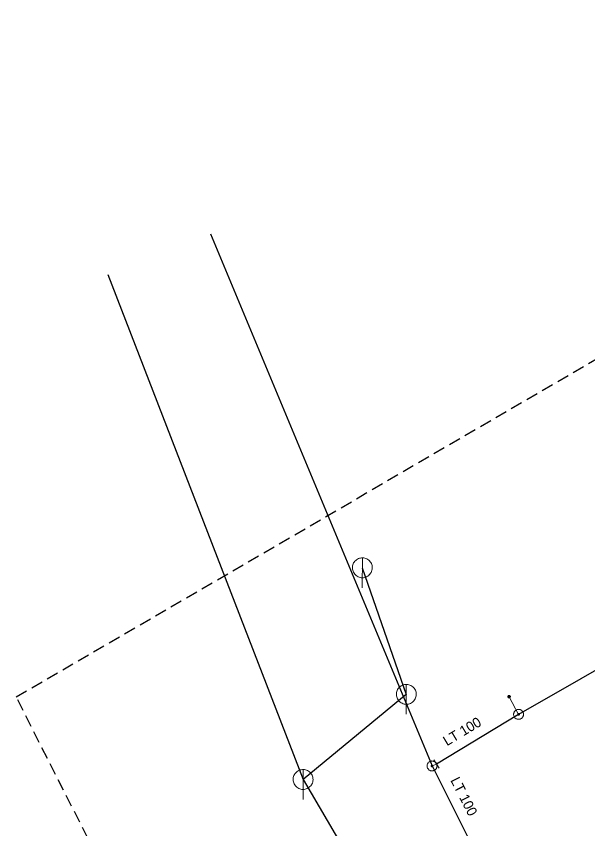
# Model space of a CAD drawing. Extents: x -689189 to -688666, y -973229 to -972850.
# Drawn here: x -689187.5 to -689130.1, y -973144.4 to -973062.7 of the extents above; entities that cross this region are included whole.
import ezdxf

# ---------------------------------------------------------------- set-up
doc = ezdxf.new("R2010")
doc.units = 0
doc.header["$LTSCALE"] = 0.4
doc.linetypes.add('MEDIUM_DASHED', pattern=[4.5, 3, -1.5])
doc.layers.add('1', color=7, linetype='Continuous')
for name, color, linetype, lineweight in [('14', 7, 'Continuous', 13), ('17', 7, 'Continuous', 25), ('22', 7, 'Continuous', 13), ('34', 7, 'Continuous', 13), ('47', 7, 'Continuous', 13), ('63', 7, 'MEDIUM_DASHED', 25), ('9', 7, 'Continuous', 13)]:
    doc.layers.add(name, color=color, linetype=linetype, lineweight=lineweight)

msp = doc.modelspace()

# ---------------------------------------------------------------- linework, layer by layer
at = {"layer": '14', "lineweight": 25}
for p, q in [((-689178.322, -973088.675), (-689158.682, -973139.478)), ((-689152.725, -973118.185), (-689148.304, -973130.915)), ((-689148.304, -973130.915), (-689158.682, -973139.478)), ((-689158.682, -973139.478), (-689148.953, -973156.032))]:
    msp.add_line(p, q, dxfattribs=at)
at = {"layer": '14'}
for p, q in [((-689137.019, -973132.93), (-689137.97, -973131.15)), ((-689145.719, -973138.12), (-689145.277, -973137.93))]:
    msp.add_line(p, q, dxfattribs=at)
at = {"layer": '17'}
for p, q in [((-689167.984, -973084.593), (-689145.719, -973138.12)), ((-689137.019, -973132.93), (-689145.277, -973137.93)), ((-689145.719, -973138.12), (-689141.14, -973147.239))]:
    msp.add_line(p, q, dxfattribs=at)
msp.add_lwpolyline([(-688981.288, -973042.24), (-688991.359, -973047.32), (-689025.954, -973066.95), (-689093.62, -973108.102), (-689137.019, -973132.93)], dxfattribs=at)
at = {"layer": '22'}
for p, q in [((-689152.725, -973120.185), (-689152.724, -973117.185)), ((-689148.304, -973132.915), (-689148.303, -973129.915)), ((-689158.682, -973141.478), (-689158.681, -973138.478))]:
    msp.add_line(p, q, dxfattribs=at)
for points in [[(-689151.725, -973118.185), (-689151.73, -973118.076), (-689151.748, -973117.968), (-689151.778, -973117.862), (-689151.818, -973117.761), (-689151.87, -973117.664), (-689151.932, -973117.574), (-689152.004, -973117.491), (-689152.084, -973117.417), (-689152.172, -973117.351), (-689152.266, -973117.296), (-689152.366, -973117.251), (-689152.471, -973117.218), (-689152.578, -973117.196), (-689152.687, -973117.186), (-689152.797, -973117.188), (-689152.905, -973117.202), (-689153.012, -973117.227), (-689153.115, -973117.264), (-689153.213, -973117.313), (-689153.305, -973117.371), (-689153.391, -973117.44), (-689153.468, -973117.517), (-689153.537, -973117.603), (-689153.596, -973117.695), (-689153.644, -973117.793), (-689153.681, -973117.896), (-689153.707, -973118.003), (-689153.721, -973118.111), (-689153.724, -973118.221), (-689153.714, -973118.33), (-689153.693, -973118.437), (-689153.659, -973118.541), (-689153.615, -973118.641), (-689153.56, -973118.736), (-689153.494, -973118.824), (-689153.42, -973118.904), (-689153.337, -973118.976), (-689153.247, -973119.038), (-689153.151, -973119.09), (-689153.049, -973119.131), (-689152.944, -973119.161), (-689152.836, -973119.179), (-689152.726, -973119.185), (-689152.617, -973119.179), (-689152.509, -973119.161), (-689152.404, -973119.132), (-689152.302, -973119.091), (-689152.205, -973119.039), (-689152.115, -973118.977), (-689152.032, -973118.906), (-689151.957, -973118.826), (-689151.892, -973118.738), (-689151.836, -973118.644), (-689151.792, -973118.544), (-689151.758, -973118.44), (-689151.736, -973118.332), (-689151.726, -973118.223)], [(-689147.304, -973130.915), (-689147.309, -973130.806), (-689147.327, -973130.698), (-689147.357, -973130.592), (-689147.397, -973130.491), (-689147.449, -973130.394), (-689147.511, -973130.304), (-689147.583, -973130.221), (-689147.663, -973130.147), (-689147.751, -973130.081), (-689147.845, -973130.026), (-689147.945, -973129.981), (-689148.05, -973129.948), (-689148.157, -973129.926), (-689148.266, -973129.916), (-689148.376, -973129.918), (-689148.484, -973129.932), (-689148.591, -973129.957), (-689148.694, -973129.994), (-689148.792, -973130.043), (-689148.884, -973130.101), (-689148.97, -973130.17), (-689149.047, -973130.247), (-689149.116, -973130.333), (-689149.175, -973130.425), (-689149.223, -973130.523), (-689149.26, -973130.626), (-689149.286, -973130.733), (-689149.3, -973130.841), (-689149.303, -973130.951), (-689149.293, -973131.06), (-689149.272, -973131.167), (-689149.238, -973131.271), (-689149.194, -973131.371), (-689149.139, -973131.466), (-689149.073, -973131.554), (-689148.999, -973131.634), (-689148.916, -973131.706), (-689148.826, -973131.768), (-689148.73, -973131.82), (-689148.628, -973131.861), (-689148.523, -973131.891), (-689148.415, -973131.909), (-689148.305, -973131.915), (-689148.196, -973131.909), (-689148.088, -973131.891), (-689147.983, -973131.862), (-689147.881, -973131.821), (-689147.784, -973131.769), (-689147.694, -973131.707), (-689147.611, -973131.636), (-689147.536, -973131.556), (-689147.471, -973131.468), (-689147.415, -973131.374), (-689147.371, -973131.274), (-689147.337, -973131.17), (-689147.315, -973131.062), (-689147.305, -973130.953)], [(-689157.682, -973139.478), (-689157.687, -973139.369), (-689157.705, -973139.261), (-689157.735, -973139.155), (-689157.775, -973139.054), (-689157.827, -973138.957), (-689157.889, -973138.867), (-689157.961, -973138.784), (-689158.041, -973138.71), (-689158.129, -973138.644), (-689158.223, -973138.589), (-689158.323, -973138.544), (-689158.428, -973138.511), (-689158.535, -973138.489), (-689158.644, -973138.479), (-689158.754, -973138.481), (-689158.862, -973138.495), (-689158.969, -973138.52), (-689159.072, -973138.557), (-689159.17, -973138.606), (-689159.262, -973138.664), (-689159.348, -973138.733), (-689159.425, -973138.81), (-689159.494, -973138.896), (-689159.553, -973138.988), (-689159.601, -973139.086), (-689159.638, -973139.189), (-689159.664, -973139.296), (-689159.678, -973139.404), (-689159.681, -973139.514), (-689159.671, -973139.623), (-689159.65, -973139.73), (-689159.616, -973139.834), (-689159.572, -973139.934), (-689159.517, -973140.029), (-689159.451, -973140.117), (-689159.377, -973140.197), (-689159.294, -973140.269), (-689159.204, -973140.331), (-689159.108, -973140.383), (-689159.006, -973140.424), (-689158.901, -973140.454), (-689158.793, -973140.472), (-689158.683, -973140.478), (-689158.574, -973140.472), (-689158.466, -973140.454), (-689158.361, -973140.425), (-689158.259, -973140.384), (-689158.162, -973140.332), (-689158.072, -973140.27), (-689157.989, -973140.199), (-689157.914, -973140.119), (-689157.849, -973140.031), (-689157.793, -973139.937), (-689157.749, -973139.837), (-689157.715, -973139.733), (-689157.693, -973139.625), (-689157.683, -973139.516)]]:
    msp.add_lwpolyline(points, close=True, dxfattribs=at)
at = {"layer": '34'}
msp.add_line((-689145.536, -973137.502), (-689145.018, -973138.357), dxfattribs=at)
at = {"layer": '47'}
for points in [[(-689136.587, -973132.676), (-689136.616, -973132.633), (-689136.65, -973132.592), (-689136.687, -973132.556), (-689136.727, -973132.523), (-689136.772, -973132.495), (-689136.819, -973132.471), (-689136.868, -973132.454), (-689136.918, -973132.44), (-689136.97, -973132.432), (-689137.022, -973132.43), (-689137.075, -973132.433), (-689137.126, -973132.442), (-689137.176, -973132.455), (-689137.225, -973132.475), (-689137.272, -973132.498), (-689137.315, -973132.527), (-689137.356, -973132.561), (-689137.393, -973132.598), (-689137.425, -973132.638), (-689137.453, -973132.683), (-689137.477, -973132.73), (-689137.495, -973132.779), (-689137.508, -973132.83), (-689137.517, -973132.881), (-689137.518, -973132.933), (-689137.515, -973132.986), (-689137.507, -973133.038), (-689137.493, -973133.087), (-689137.473, -973133.136), (-689137.45, -973133.183), (-689137.421, -973133.226), (-689137.387, -973133.267), (-689137.35, -973133.304), (-689137.31, -973133.336), (-689137.265, -973133.364), (-689137.219, -973133.388), (-689137.17, -973133.407), (-689137.119, -973133.42), (-689137.067, -973133.428), (-689137.015, -973133.429), (-689136.962, -973133.426), (-689136.911, -973133.418), (-689136.861, -973133.404), (-689136.812, -973133.384), (-689136.765, -973133.361), (-689136.722, -973133.332), (-689136.681, -973133.298), (-689136.645, -973133.262), (-689136.612, -973133.221), (-689136.584, -973133.176), (-689136.56, -973133.13), (-689136.542, -973133.081), (-689136.529, -973133.03), (-689136.521, -973132.978), (-689136.519, -973132.926), (-689136.522, -973132.873), (-689136.53, -973132.823), (-689136.544, -973132.772), (-689136.564, -973132.723)], [(-689136.948, -973132.888), (-689136.952, -973132.88), (-689136.958, -973132.874), (-689136.964, -973132.868), (-689136.971, -973132.863), (-689136.978, -973132.858), (-689136.986, -973132.855), (-689136.994, -973132.851), (-689137.002, -973132.849), (-689137.011, -973132.848), (-689137.019, -973132.848), (-689137.028, -973132.848), (-689137.036, -973132.85), (-689137.044, -973132.852), (-689137.052, -973132.854), (-689137.06, -973132.859), (-689137.068, -973132.863), (-689137.074, -973132.869), (-689137.08, -973132.875), (-689137.085, -973132.882), (-689137.09, -973132.889), (-689137.093, -973132.897), (-689137.097, -973132.905), (-689137.099, -973132.913), (-689137.101, -973132.922), (-689137.1, -973132.93), (-689137.1, -973132.939), (-689137.098, -973132.947), (-689137.096, -973132.955), (-689137.094, -973132.963), (-689137.089, -973132.971), (-689137.085, -973132.979), (-689137.079, -973132.985), (-689137.073, -973132.991), (-689137.066, -973132.996), (-689137.059, -973133.001), (-689137.052, -973133.005), (-689137.043, -973133.008), (-689137.035, -973133.01), (-689137.026, -973133.012), (-689137.018, -973133.011), (-689137.009, -973133.011), (-689137.001, -973133.009), (-689136.993, -973133.007), (-689136.985, -973133.005), (-689136.977, -973133), (-689136.969, -973132.996), (-689136.963, -973132.99), (-689136.957, -973132.984), (-689136.952, -973132.977), (-689136.947, -973132.97), (-689136.943, -973132.963), (-689136.94, -973132.954), (-689136.938, -973132.946), (-689136.937, -973132.937), (-689136.937, -973132.929), (-689136.937, -973132.92), (-689136.939, -973132.912), (-689136.941, -973132.904), (-689136.943, -973132.896)], [(-689145.51, -973138.574), (-689145.464, -973138.549), (-689145.42, -973138.521), (-689145.38, -973138.487), (-689145.343, -973138.45), (-689145.311, -973138.409), (-689145.283, -973138.364), (-689145.26, -973138.317), (-689145.242, -973138.268), (-689145.229, -973138.218), (-689145.221, -973138.166), (-689145.218, -973138.113), (-689145.223, -973138.061), (-689145.231, -973138.01), (-689145.245, -973137.959), (-689145.264, -973137.911), (-689145.289, -973137.865), (-689145.317, -973137.821), (-689145.351, -973137.78), (-689145.388, -973137.744), (-689145.429, -973137.712), (-689145.474, -973137.684), (-689145.521, -973137.66), (-689145.57, -973137.642), (-689145.62, -973137.629), (-689145.672, -973137.622), (-689145.725, -973137.619), (-689145.777, -973137.623), (-689145.828, -973137.632), (-689145.879, -973137.646), (-689145.927, -973137.665), (-689145.973, -973137.69), (-689146.017, -973137.718), (-689146.058, -973137.752), (-689146.094, -973137.789), (-689146.126, -973137.83), (-689146.155, -973137.874), (-689146.178, -973137.921), (-689146.196, -973137.97), (-689146.209, -973138.021), (-689146.216, -973138.073), (-689146.219, -973138.126), (-689146.216, -973138.177), (-689146.206, -973138.229), (-689146.192, -973138.28), (-689146.173, -973138.328), (-689146.148, -973138.374), (-689146.12, -973138.418), (-689146.087, -973138.458), (-689146.049, -973138.495), (-689146.008, -973138.527), (-689145.964, -973138.556), (-689145.917, -973138.578), (-689145.868, -973138.596), (-689145.817, -973138.609), (-689145.765, -973138.617), (-689145.712, -973138.62), (-689145.661, -973138.616), (-689145.609, -973138.607), (-689145.558, -973138.593)], [(-689145.684, -973138.194), (-689145.676, -973138.19), (-689145.67, -973138.185), (-689145.663, -973138.18), (-689145.657, -973138.174), (-689145.652, -973138.167), (-689145.647, -973138.159), (-689145.643, -973138.152), (-689145.64, -973138.144), (-689145.638, -973138.136), (-689145.637, -973138.127), (-689145.637, -973138.118), (-689145.637, -973138.11), (-689145.639, -973138.102), (-689145.64, -973138.093), (-689145.644, -973138.085), (-689145.648, -973138.077), (-689145.653, -973138.071), (-689145.658, -973138.064), (-689145.664, -973138.058), (-689145.671, -973138.053), (-689145.679, -973138.048), (-689145.686, -973138.044), (-689145.694, -973138.041), (-689145.703, -973138.039), (-689145.711, -973138.038), (-689145.72, -973138.038), (-689145.728, -973138.038), (-689145.736, -973138.04), (-689145.745, -973138.041), (-689145.753, -973138.045), (-689145.761, -973138.049), (-689145.767, -973138.054), (-689145.774, -973138.059), (-689145.78, -973138.065), (-689145.785, -973138.072), (-689145.79, -973138.079), (-689145.794, -973138.087), (-689145.797, -973138.095), (-689145.799, -973138.104), (-689145.8, -973138.112), (-689145.8, -973138.121), (-689145.8, -973138.129), (-689145.798, -973138.137), (-689145.797, -973138.146), (-689145.793, -973138.154), (-689145.789, -973138.162), (-689145.784, -973138.168), (-689145.779, -973138.175), (-689145.773, -973138.181), (-689145.766, -973138.186), (-689145.759, -973138.191), (-689145.751, -973138.195), (-689145.743, -973138.198), (-689145.735, -973138.2), (-689145.726, -973138.201), (-689145.717, -973138.201), (-689145.709, -973138.201), (-689145.701, -973138.199), (-689145.692, -973138.198)]]:
    msp.add_lwpolyline(points, close=True, dxfattribs=at)
at = {"layer": '63'}
msp.add_lwpolyline([(-689164.065, -973177.51), (-689187.511, -973131.176), (-688767.155, -972886.107), (-688767.155, -972886.107), (-688777.761, -972958.121), (-688777.761, -972958.121), (-688989.335, -973072.002), (-688989.335, -973072.002)], close=True, dxfattribs=at)
at = {"layer": '9'}
for points in [[(-689138.096, -973131.15), (-689138.096, -973131.163), (-689138.093, -973131.176), (-689138.091, -973131.189), (-689138.086, -973131.201), (-689138.08, -973131.213), (-689138.073, -973131.224), (-689138.065, -973131.234), (-689138.054, -973131.244), (-689138.044, -973131.252), (-689138.034, -973131.259), (-689138.022, -973131.265), (-689138.01, -973131.27), (-689137.997, -973131.273), (-689137.983, -973131.275), (-689137.971, -973131.277), (-689137.958, -973131.276), (-689137.945, -973131.274), (-689137.932, -973131.271), (-689137.919, -973131.266), (-689137.907, -973131.26), (-689137.897, -973131.253), (-689137.887, -973131.245), (-689137.877, -973131.235), (-689137.869, -973131.225), (-689137.862, -973131.214), (-689137.856, -973131.202), (-689137.851, -973131.19), (-689137.848, -973131.177), (-689137.846, -973131.164), (-689137.843, -973131.151), (-689137.845, -973131.138), (-689137.847, -973131.125), (-689137.85, -973131.112), (-689137.855, -973131.1), (-689137.86, -973131.088), (-689137.868, -973131.077), (-689137.875, -973131.067), (-689137.886, -973131.057), (-689137.896, -973131.049), (-689137.907, -973131.042), (-689137.919, -973131.036), (-689137.931, -973131.031), (-689137.944, -973131.028), (-689137.956, -973131.026), (-689137.97, -973131.025), (-689137.983, -973131.025), (-689137.995, -973131.027), (-689138.009, -973131.03), (-689138.021, -973131.035), (-689138.032, -973131.041), (-689138.044, -973131.048), (-689138.054, -973131.056), (-689138.064, -973131.066), (-689138.071, -973131.076), (-689138.079, -973131.087), (-689138.085, -973131.099), (-689138.09, -973131.111), (-689138.093, -973131.124), (-689138.095, -973131.137)], [(-689138.076, -973131.15), (-689138.076, -973131.161), (-689138.075, -973131.172), (-689138.071, -973131.183), (-689138.068, -973131.193), (-689138.063, -973131.203), (-689138.057, -973131.212), (-689138.049, -973131.221), (-689138.042, -973131.229), (-689138.032, -973131.236), (-689138.024, -973131.242), (-689138.014, -973131.247), (-689138.004, -973131.251), (-689137.993, -973131.254), (-689137.982, -973131.257), (-689137.971, -973131.257), (-689137.96, -973131.257), (-689137.949, -973131.255), (-689137.938, -973131.252), (-689137.928, -973131.248), (-689137.918, -973131.243), (-689137.909, -973131.237), (-689137.9, -973131.23), (-689137.892, -973131.222), (-689137.885, -973131.213), (-689137.879, -973131.204), (-689137.874, -973131.194), (-689137.87, -973131.184), (-689137.867, -973131.173), (-689137.865, -973131.162), (-689137.864, -973131.151), (-689137.864, -973131.14), (-689137.865, -973131.129), (-689137.869, -973131.118), (-689137.873, -973131.108), (-689137.878, -973131.098), (-689137.884, -973131.089), (-689137.891, -973131.08), (-689137.899, -973131.072), (-689137.907, -973131.065), (-689137.917, -973131.059), (-689137.927, -973131.054), (-689137.936, -973131.05), (-689137.948, -973131.047), (-689137.958, -973131.045), (-689137.97, -973131.045), (-689137.981, -973131.044), (-689137.992, -973131.046), (-689138.003, -973131.049), (-689138.012, -973131.053), (-689138.022, -973131.058), (-689138.032, -973131.064), (-689138.041, -973131.071), (-689138.049, -973131.079), (-689138.056, -973131.088), (-689138.061, -973131.097), (-689138.066, -973131.107), (-689138.071, -973131.117), (-689138.074, -973131.128), (-689138.076, -973131.139)], [(-689138.057, -973131.15), (-689138.057, -973131.159), (-689138.056, -973131.168), (-689138.053, -973131.177), (-689138.049, -973131.185), (-689138.046, -973131.193), (-689138.041, -973131.201), (-689138.034, -973131.208), (-689138.029, -973131.214), (-689138.022, -973131.22), (-689138.014, -973131.225), (-689138.005, -973131.229), (-689137.998, -973131.232), (-689137.989, -973131.235), (-689137.98, -973131.236), (-689137.971, -973131.238), (-689137.962, -973131.237), (-689137.953, -973131.236), (-689137.944, -973131.233), (-689137.936, -973131.23), (-689137.928, -973131.226), (-689137.919, -973131.221), (-689137.913, -973131.215), (-689137.907, -973131.209), (-689137.901, -973131.202), (-689137.896, -973131.194), (-689137.892, -973131.186), (-689137.889, -973131.178), (-689137.886, -973131.169), (-689137.885, -973131.16), (-689137.882, -973131.151), (-689137.884, -973131.142), (-689137.885, -973131.133), (-689137.887, -973131.124), (-689137.891, -973131.116), (-689137.895, -973131.108), (-689137.9, -973131.1), (-689137.906, -973131.093), (-689137.912, -973131.087), (-689137.919, -973131.081), (-689137.927, -973131.076), (-689137.934, -973131.072), (-689137.943, -973131.069), (-689137.951, -973131.066), (-689137.961, -973131.065), (-689137.97, -973131.064), (-689137.978, -973131.064), (-689137.988, -973131.065), (-689137.997, -973131.068), (-689138.005, -973131.071), (-689138.012, -973131.075), (-689138.021, -973131.08), (-689138.027, -973131.086), (-689138.034, -973131.092), (-689138.039, -973131.099), (-689138.044, -973131.107), (-689138.049, -973131.115), (-689138.052, -973131.123), (-689138.054, -973131.132), (-689138.056, -973131.141)], [(-689138.037, -973131.15), (-689138.037, -973131.157), (-689138.036, -973131.164), (-689138.034, -973131.171), (-689138.032, -973131.177), (-689138.029, -973131.183), (-689138.025, -973131.189), (-689138.021, -973131.195), (-689138.016, -973131.2), (-689138.01, -973131.204), (-689138.004, -973131.208), (-689137.998, -973131.211), (-689137.992, -973131.214), (-689137.985, -973131.215), (-689137.978, -973131.218), (-689137.971, -973131.218), (-689137.963, -973131.218), (-689137.956, -973131.216), (-689137.95, -973131.215), (-689137.944, -973131.212), (-689137.936, -973131.209), (-689137.932, -973131.205), (-689137.926, -973131.201), (-689137.921, -973131.196), (-689137.917, -973131.19), (-689137.913, -973131.184), (-689137.909, -973131.178), (-689137.907, -973131.172), (-689137.905, -973131.165), (-689137.904, -973131.158), (-689137.902, -973131.151), (-689137.902, -973131.144), (-689137.904, -973131.137), (-689137.906, -973131.13), (-689137.909, -973131.124), (-689137.912, -973131.117), (-689137.916, -973131.112), (-689137.919, -973131.106), (-689137.924, -973131.101), (-689137.931, -973131.097), (-689137.936, -973131.093), (-689137.943, -973131.09), (-689137.949, -973131.087), (-689137.956, -973131.085), (-689137.963, -973131.084), (-689137.97, -973131.084), (-689137.977, -973131.084), (-689137.983, -973131.084), (-689137.99, -973131.086), (-689137.997, -973131.089), (-689138.003, -973131.092), (-689138.009, -973131.096), (-689138.015, -973131.1), (-689138.02, -973131.105), (-689138.024, -973131.111), (-689138.027, -973131.116), (-689138.031, -973131.123), (-689138.034, -973131.129), (-689138.034, -973131.136), (-689138.037, -973131.143)], [(-689138.017, -973131.15), (-689138.017, -973131.155), (-689138.017, -973131.16), (-689138.016, -973131.165), (-689138.014, -973131.169), (-689138.012, -973131.174), (-689138.009, -973131.178), (-689138.005, -973131.181), (-689138.002, -973131.185), (-689137.999, -973131.188), (-689137.995, -973131.191), (-689137.99, -973131.193), (-689137.985, -973131.195), (-689137.981, -973131.196), (-689137.976, -973131.198), (-689137.971, -973131.198), (-689137.966, -973131.198), (-689137.961, -973131.197), (-689137.956, -973131.196), (-689137.951, -973131.194), (-689137.946, -973131.192), (-689137.943, -973131.189), (-689137.939, -973131.186), (-689137.936, -973131.182), (-689137.933, -973131.179), (-689137.929, -973131.175), (-689137.928, -973131.17), (-689137.926, -973131.166), (-689137.924, -973131.161), (-689137.924, -973131.156), (-689137.923, -973131.151), (-689137.923, -973131.146), (-689137.924, -973131.141), (-689137.924, -973131.136), (-689137.927, -973131.132), (-689137.929, -973131.127), (-689137.932, -973131.123), (-689137.934, -973131.119), (-689137.938, -973131.116), (-689137.941, -973131.113), (-689137.946, -973131.11), (-689137.951, -973131.108), (-689137.955, -973131.106), (-689137.96, -973131.105), (-689137.965, -973131.104), (-689137.97, -973131.104), (-689137.975, -973131.104), (-689137.98, -973131.105), (-689137.985, -973131.105), (-689137.989, -973131.107), (-689137.994, -973131.109), (-689137.998, -973131.112), (-689138, -973131.115), (-689138.005, -973131.118), (-689138.007, -973131.122), (-689138.011, -973131.126), (-689138.012, -973131.131), (-689138.015, -973131.135), (-689138.016, -973131.14), (-689138.017, -973131.145)], [(-689137.997, -973131.15), (-689137.997, -973131.153), (-689137.998, -973131.156), (-689137.997, -973131.158), (-689137.995, -973131.161), (-689137.995, -973131.164), (-689137.993, -973131.166), (-689137.99, -973131.168), (-689137.989, -973131.17), (-689137.987, -973131.172), (-689137.985, -973131.174), (-689137.982, -973131.176), (-689137.978, -973131.177), (-689137.977, -973131.177), (-689137.973, -973131.178), (-689137.971, -973131.178), (-689137.968, -973131.178), (-689137.965, -973131.178), (-689137.962, -973131.177), (-689137.96, -973131.176), (-689137.956, -973131.175), (-689137.955, -973131.173), (-689137.951, -973131.171), (-689137.95, -973131.169), (-689137.949, -973131.167), (-689137.946, -973131.165), (-689137.946, -973131.162), (-689137.944, -973131.159), (-689137.944, -973131.157), (-689137.943, -973131.154), (-689137.941, -973131.151), (-689137.943, -973131.148), (-689137.943, -973131.145), (-689137.944, -973131.142), (-689137.945, -973131.14), (-689137.946, -973131.137), (-689137.948, -973131.135), (-689137.949, -973131.132), (-689137.951, -973131.13), (-689137.954, -973131.129), (-689137.956, -973131.127), (-689137.958, -973131.126), (-689137.961, -973131.125), (-689137.963, -973131.124), (-689137.967, -973131.124), (-689137.97, -973131.123), (-689137.973, -973131.124), (-689137.976, -973131.123), (-689137.978, -973131.125), (-689137.981, -973131.125), (-689137.983, -973131.126), (-689137.985, -973131.128), (-689137.988, -973131.129), (-689137.99, -973131.131), (-689137.992, -973131.134), (-689137.994, -973131.136), (-689137.995, -973131.139), (-689137.995, -973131.141), (-689137.997, -973131.144), (-689137.997, -973131.147)], [(-689137.978, -973131.15), (-689137.978, -973131.152), (-689137.978, -973131.152), (-689137.977, -973131.152), (-689137.977, -973131.154), (-689137.978, -973131.155), (-689137.976, -973131.155), (-689137.976, -973131.155), (-689137.976, -973131.157), (-689137.976, -973131.157), (-689137.975, -973131.158), (-689137.973, -973131.158), (-689137.973, -973131.158), (-689137.973, -973131.159), (-689137.971, -973131.159), (-689137.971, -973131.159), (-689137.97, -973131.159), (-689137.968, -973131.159), (-689137.968, -973131.158), (-689137.968, -973131.158), (-689137.966, -973131.158), (-689137.966, -973131.157), (-689137.966, -973131.157), (-689137.965, -973131.156), (-689137.965, -973131.156), (-689137.963, -973131.155), (-689137.963, -973131.154), (-689137.962, -973131.153), (-689137.962, -973131.153), (-689137.962, -973131.152), (-689137.962, -973131.151), (-689137.962, -973131.15), (-689137.962, -973131.149), (-689137.962, -973131.149), (-689137.963, -973131.148), (-689137.963, -973131.147), (-689137.963, -973131.146), (-689137.963, -973131.146), (-689137.965, -973131.145), (-689137.965, -973131.145), (-689137.966, -973131.144), (-689137.967, -973131.144), (-689137.968, -973131.143), (-689137.968, -973131.143), (-689137.968, -973131.143), (-689137.97, -973131.143), (-689137.971, -973131.143), (-689137.972, -973131.143), (-689137.972, -973131.143), (-689137.973, -973131.144), (-689137.973, -973131.143), (-689137.975, -973131.145), (-689137.975, -973131.145), (-689137.976, -973131.145), (-689137.976, -973131.145), (-689137.977, -973131.147), (-689137.977, -973131.148), (-689137.977, -973131.149), (-689137.978, -973131.149), (-689137.978, -973131.15)]]:
    msp.add_lwpolyline(points, close=True, dxfattribs=at)

# ---------------------------------------------------------------- texts
at = {"layer": '1'}
for rotation, p in [(31, (-689144.224, -973136.141)), (297, (-689143.895, -973139.556))]:
    msp.add_text('LT 100', height=1, rotation=rotation, dxfattribs=at).set_placement(p)

doc.saveas('drawing.dxf')
